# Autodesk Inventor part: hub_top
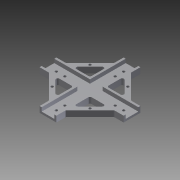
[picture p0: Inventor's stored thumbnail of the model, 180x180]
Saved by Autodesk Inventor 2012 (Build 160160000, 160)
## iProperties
Created: 2011-06
Part Number: hub_top
Document SubType Name: Modeling
Designer: Bruce
Density: 1 g/cm^3
Material: Default
Author: Bruce
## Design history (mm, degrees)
sketch "Sketch1"
  geometry: L1 (-50, 50)-(50, 50); L2 (50, 50)-(50, -50); L3 (50, -50)-(-50, -50); L4 (-50, -50)-(-50, 50); L5 (-50, 0)-(50, 0); L6 (0, 50)-(0, -50); L7 (-10, 50)-(-10, 10); L8 (-10, 10)-(-50, 10); L9 (10, 50)-(10, 10); L10 (10, 10)-(50, 10); L11 (50, -10)-(10, -10); L12 (10, -10)-(10, -50); L13 (-10, -50)-(-10, -10); L14 (-10, -10)-(-50, -10); L15 (-10, 50)-(10, 50); L16 (50, 10)-(50, -10); L17 (10, -50)-(-10, -50); L18 (-50, 10)-(-50, -10); 1 further point
  constraints: 36 end point, 8 point on line, 6 perpendicular, 5 parallel, 4 collinear, 4 midpoint, 1 horizontal
  dimensions: "d0" = 50 distance from line of L1 point (0, 0) (= 0.5 x hub_square); "d1" = 50 distance from line of L3 point (0, 0) (= 0.5 x hub_square); "d2" = 50 distance from line of L2 point (0, 0) (= 0.5 x hub_square); "d3" = 50 distance from line of point (0, 0) L4 (= 0.5 x hub_square); "d4" = 10 distance between parallel lines of L6 L7 (= 0.5 x arm_width + structural_cover); "d5" = 10 distance between parallel lines of L6 L9 (= 0.5 x arm_width + structural_cover); "d6" = 10 distance between parallel lines of L5 L8 (= 0.5 x arm_width + structural_cover); "d7" = 10 distance between parallel lines of L14 L5 (= 0.5 x arm_width + structural_cover); "d8" = 10 distance between parallel lines of L6 L13 (= 0.5 x arm_width + structural_cover); "d9" = 10 distance between parallel lines of L12 L6 (= 0.5 x arm_width + structural_cover); "d10" = 10 distance between parallel lines of L11 L5 (= 0.5 x arm_width + structural_cover); "d11" = 10 distance between parallel lines of L10 L5 (= 0.5 x arm_width + structural_cover)
extrude "Extrusion1" new body sketch "Sketch1" distance "d12" = 2.5 (= structural_cover); taper "d13" = 0 deg
sketch "Sketch2"
  geometry: L1 (-10, 50)-(10, 50) reference; L2 (-10, 10)-(-10, 50) reference; L3 (-50, 10)-(-10, 10) reference; L4 (-50, -10)-(-50, 10) reference; L5 (-10, -10)-(-50, -10) reference; L6 (-10, -50)-(-10, -10) reference; L7 (10, -50)-(-10, -50) reference; L8 (10, -10)-(10, -50) reference; L9 (50, -10)-(10, -10) reference; L10 (50, 10)-(50, -10) reference; L11 (10, 10)-(50, 10) reference; L12 (10, 50)-(10, 10) reference; L13 (-7.5, 50)-(-7.5, 7.5); L14 (-7.5, 7.5)-(-50, 7.5); L15 (-50, -7.5)-(-7.5, -7.5); L16 (-7.5, -7.5)-(-7.5, -50); L17 (50, -7.5)-(7.5, -7.5); L18 (7.5, -7.5)-(7.5, -50); L19 (50, 7.5)-(7.5, 7.5); L20 (7.5, 7.5)-(7.5, 50); L21 (-7.5, 50)-(-10, 50); L22 (-10, 10)-(-50, 10); L23 (-50, 7.5)-(-50, 10); L24 (-50, -7.5)-(-50, -10); L25 (-50, -10)-(-10, -10); L26 (-10, -10)-(-10, -50); L27 (-10, -50)-(-7.5, -50); L28 (7.5, -50)-(10, -50); L29 (10, -50)-(10, -10); L30 (10, -10)-(50, -10); L31 (50, -10)-(50, -7.5); L32 (50, 7.5)-(50, 10); L33 (50, 10)-(10, 10); L34 (10, 10)-(10, 50); L35 (10, 50)-(7.5, 50); L36 (-10, 50)-(-10, 10); L37 (-50, 0)-(50, 0); L38 (0, 50)-(0, -50); L39 (-20, 7.5)-(-20, -7.5); L40 (20, 7.5)-(20, -7.5); L41 (-7.5, 20)-(7.5, 20); L42 (-7.5, -20)-(7.5, -20); 1 further point
  constraints: 60 end point, 16 point on line, 13 collinear, 13 perpendicular, 4 midpoint, 2 parallel
  dimensions: "d14" = 2.5 distance between parallel lines of L13 L2 (= structural_cover); "d15" = 2.5 distance between parallel lines of L14 L3 (= structural_cover); "d16" = 2.5 distance between parallel lines of L5 L15 (= structural_cover); "d17" = 2.5 distance between parallel lines of L16 L6 (= structural_cover); "d18" = 2.5 distance between parallel lines of L8 L18 (= structural_cover); "d19" = 2.5 distance between parallel lines of L9 L17 (= structural_cover); "d20" = 2.5 distance between parallel lines of L19 L11 (= structural_cover); "d21" = 2.5 distance between parallel lines of L12 L20 (= structural_cover); "d42" = 30 distance between parallel lines of L4 L39 (= 3 x arm_fixing_spacing); "d43" = 30 distance between parallel lines of L1 L41 (= 3 x arm_fixing_spacing); "d44" = 30 distance between parallel lines of L10 L40 (= 3 x arm_fixing_spacing); "d45" = 30 distance between parallel lines of L7 L42 (= 3 x arm_fixing_spacing)
extrude "Extrusion2" join sketch "Sketch2" distance "d22" = 4.5 (= -0.5 x pinch_gap + 0.5 x arm_height); taper "d23" = 0 deg
sketch "Sketch3"
  geometry: L1 (-10, 50)-(10, 50) reference; L2 (-50, -10)-(-50, 10) reference; L3 (10, -50)-(-10, -50) reference; L4 (50, 10)-(50, -10) reference; L5 (0, 50)-(0, -50); L6 (-50, 0)-(50, 0); C1 r 1.5 at (-40, 0); C2 r 1.5 at (-30, 0); C3 r 1.5 at (0, 40); C4 r 1.5 at (0, 30); C5 r 1.5 at (0, -40); C6 r 1.5 at (0, -30); C7 r 1.5 at (40, 0); C8 r 1.5 at (30, 0); 1 further point
  constraints: 8 centre point, 8 point on line, 4 end point, 4 midpoint
  dimensions: "d24" = 3 diameter of C1 (= arm_bolt_diam); "d25" = 3 diameter of C2 (= arm_bolt_diam); "d26" = 3 diameter of C3 (= arm_bolt_diam); "d27" = 3 diameter of C4 (= arm_bolt_diam); "d28" = 3 diameter of C8 (= arm_bolt_diam); "d29" = 3 diameter of C7 (= arm_bolt_diam); "d30" = 3 diameter of C6 (= arm_bolt_diam); "d31" = 3 diameter of C5 (= arm_bolt_diam); "d32" = 10 distance from line of C1.centre L2 (= arm_fixing_spacing); "d33" = 10 distance of C2.centre C1.centre (= arm_fixing_spacing); "d34" = 10 distance from line of L1 C3.centre (= arm_fixing_spacing); "d35" = 10 distance of C3.centre C4.centre (= arm_fixing_spacing); "d36" = 10 distance from line of L4 C7.centre (= arm_fixing_spacing); "d37" = 10 distance of C7.centre C8.centre (= arm_fixing_spacing); "d38" = 10 distance of C5.centre C6.centre (= arm_fixing_spacing); "d39" = 10 distance from line of C5.centre L3 (= arm_fixing_spacing)
extrude "Extrusion3" cut sketch "Sketch3" distance "d40" = 2.5 (= structural_cover); taper "d41" = 0 deg
sketch "Sketch4"
  geometry: L1 (10, 50)-(10, 10) reference; L2 (-10, 50)-(10, 50) reference; L3 (-10, 10)-(-10, 50) reference; L4 (-50, 10)-(-10, 10) reference; L5 (-50, -10)-(-50, 10) reference; L6 (-10, -10)-(-50, -10) reference; L7 (-10, -50)-(-10, -10) reference; L8 (10, -50)-(-10, -50) reference; L9 (10, -10)-(10, -50) reference; L10 (50, -10)-(10, -10) reference; L11 (50, 10)-(50, -10) reference; L12 (10, 10)-(50, 10) reference; L13 (-22.5, 22.5)-(22.5, 22.5); L14 (22.5, 22.5)-(22.5, -22.5); L15 (22.5, -22.5)-(-22.5, -22.5); L16 (-22.5, -22.5)-(-22.5, 22.5); L17 (-50, 0)-(50, 0); L18 (0, 50)-(0, -50); L19 (-31.111, 10)-(-10, 31.111); L20 (-38.889, 10)-(-10, 38.889); L21 (-10, 38.889)-(-10, 31.111); L22 (-38.889, 10)-(-31.111, 10); L23 (31.111, 10)-(10, 31.111); L24 (10, 38.889)-(38.889, 10); L25 (31.111, -10)-(10, -31.111); L26 (38.889, -10)-(10, -38.889); L27 (-10, -31.111)-(-31.111, -10); L28 (-38.889, -10)-(-10, -38.889); L29 (-38.889, -10)-(-31.111, -10); L30 (-10, -31.111)-(-10, -38.889); L31 (10, -31.111)-(10, -38.889); L32 (31.111, -10)-(38.889, -10); L33 (31.111, 10)-(38.889, 10); L34 (10, 38.889)-(10, 31.111); C1 r 1.5 at (-22.5, 22.5); C2 r 1.5 at (22.5, 22.5); C3 r 1.5 at (-22.5, -22.5); C4 r 1.5 at (22.5, -22.5); 1 further point
  constraints: 44 end point, 16 point on line, 5 collinear, 4 centre point, 4 coincident, 4 midpoint, 4 parallel, 4 perpendicular, 1 horizontal
  dimensions: "d46" = 45 distance between parallel lines of L14 L16 (= mounting_square); "d47" = 45 distance between parallel lines of L15 L13 (= mounting_square); "d48" = 22.5 distance between parallel lines of L14 L18 (= 0.5 x mounting_square); "d49" = 22.5 distance between parallel lines of L13 L17 (= 0.5 x mounting_square); "d50" = 3 diameter of C3 (= mounting_bolt_diam); "d51" = 3 diameter of C4 (= mounting_bolt_diam); "d52" = 3 diameter of C2 (= mounting_bolt_diam); "d53" = 3 diameter of C1 (= mounting_bolt_diam); "d54" = 45 deg angle of L4 L19; "d55" = 2.75 distance from line of L19 L13.start (= 0.5 x mounting_bolt_diam + 0.5 x structural_cover); "d56" = 45 deg angle of L4 L20; "d57" = 2.75 distance from line of L20 L13.start (= 0.5 x mounting_bolt_diam + 0.5 x structural_cover); "d58" = 45 deg angle of L12 L23; "d59" = 2.75 distance from line of L23 L13.end (= 0.5 x mounting_bolt_diam + 0.5 x structural_cover); "d60" = 45 deg angle of L12 L24; "d61" = 2.75 distance from line of L24 L13.end (= 0.5 x mounting_bolt_diam + 0.5 x structural_cover); "d62" = 45 deg angle of L10 L25; "d63" = 2.75 distance from line of L26 L14.end (= 0.5 x mounting_bolt_diam + 0.5 x structural_cover); "d64" = 2.75 distance from line of L14.end L25 (= 0.5 x mounting_bolt_diam + 0.5 x structural_cover); "d65" = 45 deg angle of L6 L28; "d66" = 2.75 distance from line of L28 C3.centre (= 0.5 x mounting_bolt_diam + 0.5 x structural_cover); "d67" = 2.75 distance from line of L27 L15.end (= 0.5 x mounting_bolt_diam + 0.5 x structural_cover)
extrude "Extrusion4" join sketch "Sketch4" distance "d68" = 7 (= 0.5 x arm_height + structural_cover - 0.5 x pinch_gap); taper "d69" = 0 deg
fillet "Fillet1" dims "d70" = 2
fillet "Fillet2" dims "d71" = 2
body "Solid1"
other parameters: "mounting_square" = 45 [user parameter; used in 4 equation terms], "arm_width" = 15 [user parameter; used in 8 equation terms], "arm_bolt_diam" = 3 [user parameter; used in 8 equation terms], "structural_cover" = 2.5 [user parameter; used in 27 equation terms], "pinch_gap" = 1 [user parameter; used in 2 equation terms], "arm_fixing_spacing" = 10 [user parameter; used in 12 equation terms], "mounting_bolt_diam" = 3 [user parameter; used in 12 equation terms]
